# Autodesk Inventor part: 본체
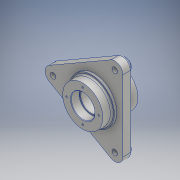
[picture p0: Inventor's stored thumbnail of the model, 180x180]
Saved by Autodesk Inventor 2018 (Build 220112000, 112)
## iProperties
Created: 2023-04
Part Number: 본체
Material: 알루미늄 6061
Document SubType Name: Modeling
Designer: home
Density: 2.7 g/cm^3
Appearance: 알루미늄 - 평지
Mass: 1219.03 g
Surface Area: 640.875 cm^2
Volume: 451.494 cm^3
Author: home
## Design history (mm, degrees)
sketch "스케치1"
  geometry: L1 (82, 0)-(-41, -71.014); L2 (-41, -71.014)-(-41, 71.014); L3 (-41, 71.014)-(82, 0); L4 (90, 13.856)-(-33, 84.87); L5 (-57, 71.014)-(-57, -71.014); L6 (90, -13.856)-(-33, -84.87); A1 r 16 centre (82, 0) between (90, 13.856) and (90, -13.856); A2 r 16 centre (-41, 71.014) between (-33, 84.87) and (-57, 71.014); A3 r 16 centre (-41, -71.014) between (-57, -71.014) and (-33, -84.87); 2 further points
  constraints: 12 end point, 6 point on circle, 6 tangent, 3 centre point, 2 coincident, 1 vertical, 7 other
  dimensions: "d1" = 32 diameter of A1; "d2" = 32 diameter of A2; "d3" = 32 diameter of A3
extrude "돌출1" new body sketch "스케치1" distance "d4" = 18; taper "d5" = 0 deg
sketch "스케치3"
  geometry: L1 (-90, -13.856)-(33, -84.87) reference; L2 (57, -71.014)-(57, 71.014) reference; L3 (33, 84.87)-(-90, 13.856) reference; C1 r 11 at (41, -71.014); C2 r 11 at (41, 71.014); C3 r 11 at (-82, 0); A1 r 16 centre (41, -71.014) between (33, -84.87) and (57, -71.014) reference; A2 r 16 centre (41, 71.014) between (57, 71.014) and (33, 84.87) reference; A3 r 16 centre (-82, 0) between (-90, 13.856) and (-90, -13.856) reference; 1 further point
  constraints: 3 centre point, 3 coincident
  dimensions: "d8" = 22 diameter of C1; "d9" = 22 diameter of C2; "d10" = 22 diameter of C3
extrude "돌출2" join sketch "스케치3" distance "d11" = 4; taper "d12" = 0 deg
hole "구멍1" diameter "d15" = 11; stored, may be unused: countersink angle "d19" = 90 deg, drill point angle "d21" = 118 deg; dims "d13" = 10, "d14" = 10, "d16" = 6, "d17" = 4, "d18" = 2, "d20" = 8
hole "구멍2" diameter "d24" = 11; stored, may be unused: countersink angle "d28" = 90 deg, drill point angle "d30" = 118 deg; dims "d22" = 10, "d23" = 10, "d25" = 6, "d26" = 4, "d27" = 2, "d29" = 8
hole "구멍3" diameter "d33" = 11; stored, may be unused: countersink angle "d37" = 90 deg, drill point angle "d39" = 118 deg; dims "d31" = 10, "d32" = 10, "d34" = 6, "d35" = 4, "d36" = 2, "d38" = 8
sketch "스케치4"
  geometry: C1 r 40 at (0, 0); 1 further point
  constraints: 1 centre point, 1 coincident
  dimensions: "d40" = 80 diameter of C1
extrude "돌출3" join sketch "스케치4" distance "d41" = 29; taper "d42" = 0 deg
sketch "스케치5"
  geometry: C1 r 45 at (0, 0); 1 further point
  constraints: 1 centre point, 1 coincident
  dimensions: "d43" = 90 diameter of C1
extrude "돌출4" join sketch "스케치5" distance "d44" = 5; taper "d45" = 0 deg
sketch "스케치6"
  geometry: C1 r 40 at (0, 0); 1 further point
  constraints: 1 centre point, 1 coincident
  dimensions: "d46" = 80 diameter of C1
extrude "돌출5" join sketch "스케치6" distance "d47" = 18; taper "d48" = 0 deg
hole "구멍4" diameter "d51" = 42; stored, may be unused: countersink angle "d55" = 90 deg, drill point angle "d57" = 118 deg; dims "d49" = 10, "d50" = 10, "d52" = 6, "d53" = 47, "d54" = 17, "d56" = 8
hole "구멍5" diameter "d60" = 42; stored, may be unused: countersink angle "d64" = 90 deg, drill point angle "d66" = 118 deg; dims "d58" = 10, "d59" = 10, "d61" = 6, "d62" = 47, "d63" = 17, "d65" = 8
chamfer "모따기1" distance "d67" = 1; stored, may be unused: second distance "d68" = 2, angle "d69" = 45 deg
fillet "모깎기1" dims "d70" = 0.6
fillet "모깎기2" dims "d71" = 3
fillet "모깎기3" dims "d72" = 3
sketch "스케치7"
  geometry: C1 r 40 at (0, 0) reference; C2 r 24.5 at (0, 0) reference; 2 further points
  dimensions: "d73" = 32 distance of point (0, 0) point (-32, 0)
hole "구멍6" sketch "스케치7" at (-32, 0) diameter "d74" = 3.242; stored, may be unused: countersink angle "d78" = 90 deg, drill point angle "d80" = 118 deg; dims "d75" = 8, "d76" = 47, "d77" = 17, "d79" = 10
fillet "모깎기4" dims "d84" = 3
sketch "스케치8"
  geometry: C1 r 40 at (0, 0) reference; C2 r 24.5 at (0, 0) reference; 2 further points
  dimensions: "d85" = 32 distance of point (0, 0) point (-32, 0)
hole "구멍7" sketch "스케치8" at (-32, 0) diameter "d86" = 3.242; stored, may be unused: countersink angle "d90" = 90 deg, drill point angle "d92" = 118 deg; dims "d87" = 8, "d88" = 47, "d89" = 17, "d91" = 10
sketch "스케치9"
  geometry: 2 further points
  constraints: 1 horizontal alignment, 1 other
  dimensions: "d96" = 60 distance of point (0, 0) point (-60, 0)
feature "엠보싱1" sketch "스케치9" dims "d97" = 0.5, "d98" = 0
node "솔리드1"
pattern_circular "원형 패턴1" dims angle "d82" = 360 deg
pattern_circular "원형 패턴2" dims angle "d94" = 360 deg
node "투영된 루프1"
node "투영된 루프2"
node "투영된 루프3"
